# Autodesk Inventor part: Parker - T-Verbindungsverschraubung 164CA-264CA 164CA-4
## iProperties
Created: 2006-08
Part Number: Parker - T-Verbindungsverschraubung 164CA-264CA 164CA-4
Material: Messing (gelb, weich)
Description: T-Verbindungsverschraubung
Document SubType Name: Modeling
Standard: Parker
Designer: Haugg
Manufacturer: Parker
Language: de-DE
Size Designation: 164CA-4
Categories: <MemberInstance Version="R10.0.0"><Categories><Category DisplayName="Rohre und Leitungen" InternalName="4347fa0f-2144-441d-94cd-e3e15c92b736" Mnemonic="TUBEANDP
_DisabledCommands: 0
NAME: PIPING: Parker Union Tee 164CA-264CA
DATA: <meta><inlinegroups number="1" deflen="4.55295"></inlinegroups><connections number="3"></connections><angles><a>3.14159265358979</a><a>1.5707963267949</a></angl
Author: Haugg
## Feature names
1. Extrusion1
2. Revolution1
3. Revolution2
4. Extrusion2
5. Extrusion3
6. Chamfer1
7. Extrusion5
8. Extrusion4
9. Circular Pattern1
10. Hole3
11. Circular Pattern2
